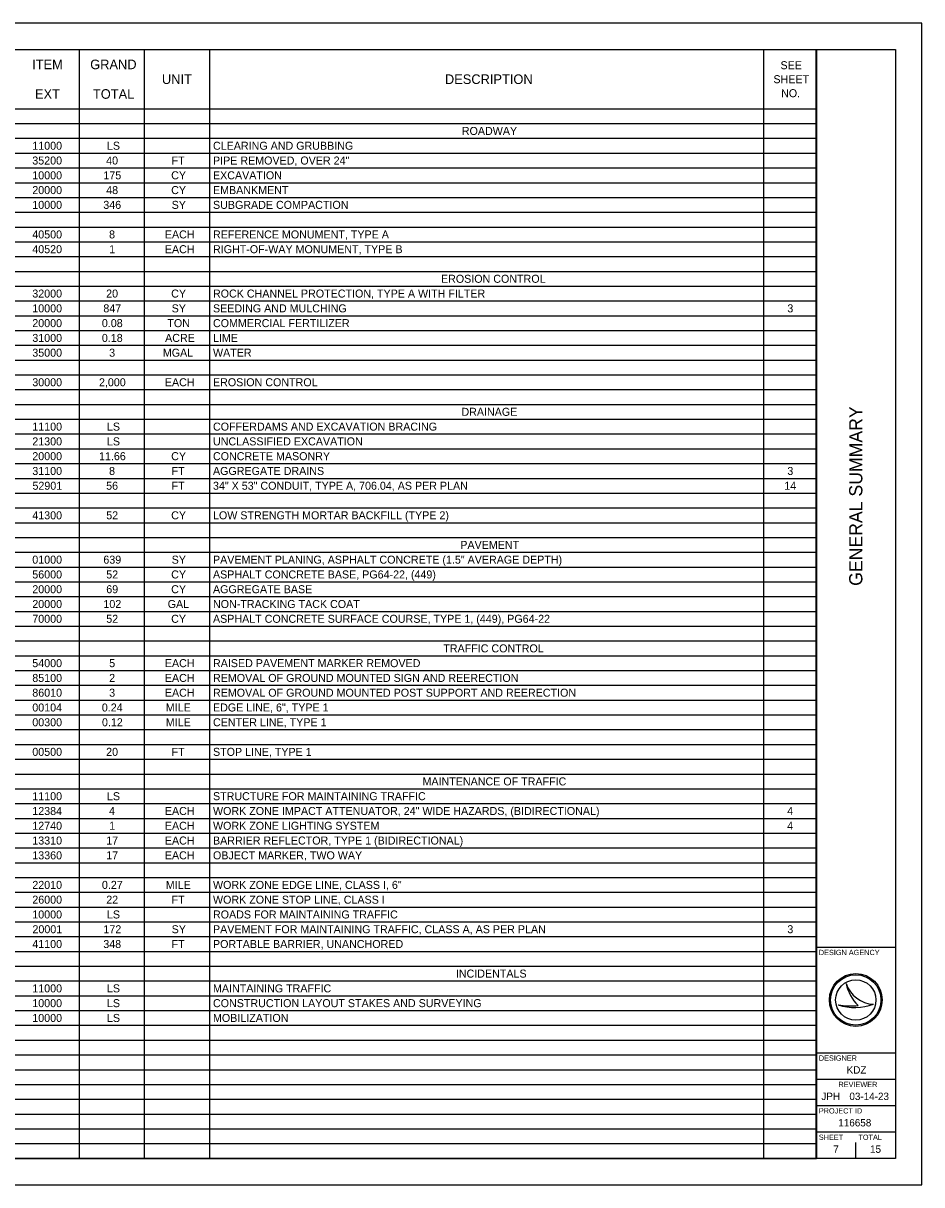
# Model space of a CAD drawing. Extents: x 0 to 34, y 0 to 22.
# Drawn here: x 16.98 to 34, y 0 to 22 of the extents above; entities that cross this region are included whole.
import ezdxf

# ---------------------------------------------------------------- set-up
doc = ezdxf.new("R2010")
doc.units = 0
for name, color, linetype in [('SH_Border', 7, 'Continuous'), ('SH_Cut_Line', 7, 'Continuous'), ('SH_Data', 7, 'Continuous'), ('SH_Text', 7, 'Continuous')]:
    doc.layers.add(name, color=color, linetype=linetype)

msp = doc.modelspace()

# ---------------------------------------------------------------- linework, layer by layer
at = {"layer": 'SH_Border'}
for p, q in [((32, 0.5), (32, 21.5)), ((32, 4.5), (33.5, 4.5)), ((32, 2.5), (33.5, 2.5)), ((32, 2), (33.5, 2)), ((32, 1.5), (33.5, 1.5)), ((32, 1), (33.5, 1))]:
    msp.add_line(p, q, dxfattribs=at)
msp.add_lwpolyline([(1.5, 21.5), (33.5, 21.5), (33.5, 0.5), (1.5, 0.5)], close=True, dxfattribs=at)
at = {"layer": 'SH_Cut_Line'}
msp.add_lwpolyline([(0, 0), (34, 0), (34, 22), (0, 22)], close=True, dxfattribs=at)
at = {"layer": 'SH_Data'}
for p, q in [((32.567, 3.81), (32.567, 3.81)), ((32.417, 3.41), (32.417, 3.41)), ((32.75, 3.5), (32.75, 3.5)), ((33.087, 3.419), (33.087, 3.419)), ((32.375, 0.675), (32.375, 0.675)), ((32.75, 0.5), (32.75, 0.8))]:
    msp.add_line(p, q, dxfattribs=at)
for radius in [0.5, 0.477, 0.477, 0.382]:
    msp.add_circle((32.75, 3.5), radius, dxfattribs=at)
for centre, radius, start, end in [((33.116, 3.998), 0.58, 198.9257, 198.9319), ((33.347, 3.97), 0.796, 191.6379, 191.6421), ((33.116, 3.998), 0.58, 198.9319, 267.1657), ((33.347, 3.97), 0.796, 191.6421, 226.0947), ((32.739, 4.37), 1.013, 251.4576, 290.0832), ((32.648, 4.654), 1.266, 259.4964, 259.4995), ((32.739, 4.37), 1.013, 251.4527, 251.4576), ((32.648, 4.654), 1.266, 259.4995, 276.6672)]:
    msp.add_arc(centre, radius, start, end, dxfattribs=at)
at = {"layer": 'SH_Text'}
for p, q in [((1.5, 21.5), (32.004, 21.5)), ((18.036, 21.5), (18.036, 0.5)), ((19.272, 21.5), (19.272, 0.5)), ((20.507, 21.5), (20.507, 0.5)), ((30.999, 21.5), (30.999, 0.5)), ((32.004, 21.5), (32.004, 0.5)), ((1.5, 20.38), (32.004, 20.38)), ((1.5, 20.1), (32.004, 20.1)), ((1.5, 19.82), (32.004, 19.82)), ((1.5, 19.54), (32.004, 19.54)), ((1.5, 19.26), (32.004, 19.26)), ((1.5, 18.98), (32.004, 18.98)), ((1.5, 18.7), (32.004, 18.7)), ((1.5, 18.42), (32.004, 18.42)), ((1.5, 18.14), (32.004, 18.14)), ((1.5, 17.86), (32.004, 17.86)), ((1.5, 17.58), (32.004, 17.58)), ((1.5, 17.3), (32.004, 17.3)), ((1.5, 17.02), (32.004, 17.02)), ((1.5, 16.74), (32.004, 16.74)), ((1.5, 16.46), (32.004, 16.46)), ((1.5, 16.18), (32.004, 16.18)), ((1.5, 15.9), (32.004, 15.9)), ((1.5, 15.62), (32.004, 15.62)), ((1.5, 15.34), (32.004, 15.34)), ((1.5, 15.06), (32.004, 15.06)), ((1.5, 14.78), (32.004, 14.78)), ((1.5, 14.5), (32.004, 14.5)), ((1.5, 14.22), (32.004, 14.22)), ((1.5, 13.94), (32.004, 13.94)), ((1.5, 13.66), (32.004, 13.66)), ((1.5, 13.38), (32.004, 13.38)), ((1.5, 13.1), (32.004, 13.1)), ((1.5, 12.82), (32.004, 12.82)), ((1.5, 12.54), (32.004, 12.54)), ((1.5, 12.26), (32.004, 12.26)), ((1.5, 11.98), (32.004, 11.98)), ((1.5, 11.7), (32.004, 11.7)), ((1.5, 11.42), (32.004, 11.42)), ((1.5, 11.14), (32.004, 11.14)), ((1.5, 10.86), (32.004, 10.86)), ((1.5, 10.58), (32.004, 10.58)), ((1.5, 10.3), (32.004, 10.3)), ((1.5, 10.02), (32.004, 10.02)), ((1.5, 9.74), (32.004, 9.74)), ((1.5, 9.46), (32.004, 9.46)), ((1.5, 9.18), (32.004, 9.18)), ((1.5, 8.9), (32.004, 8.9)), ((1.5, 8.62), (32.004, 8.62)), ((1.5, 8.34), (32.004, 8.34)), ((1.5, 8.06), (32.004, 8.06)), ((1.5, 7.78), (32.004, 7.78)), ((1.5, 7.5), (32.004, 7.5)), ((1.5, 7.22), (32.004, 7.22)), ((1.5, 6.94), (32.004, 6.94)), ((1.5, 6.66), (32.004, 6.66)), ((1.5, 6.38), (32.004, 6.38)), ((1.5, 6.1), (32.004, 6.1)), ((1.5, 5.82), (32.004, 5.82)), ((1.5, 5.54), (32.004, 5.54)), ((1.5, 5.26), (32.004, 5.26)), ((1.5, 4.98), (32.004, 4.98)), ((1.5, 4.7), (32.004, 4.7)), ((1.5, 4.42), (32.004, 4.42)), ((1.5, 4.14), (32.004, 4.14)), ((1.5, 3.86), (32.004, 3.86)), ((1.5, 3.58), (32.004, 3.58)), ((1.5, 3.3), (32.004, 3.3)), ((1.5, 3.02), (32.004, 3.02)), ((1.5, 2.74), (32.004, 2.74)), ((1.5, 2.46), (32.004, 2.46)), ((1.5, 2.18), (32.004, 2.18)), ((1.5, 1.9), (32.004, 1.9)), ((1.5, 1.62), (32.004, 1.62)), ((1.5, 1.34), (32.004, 1.34)), ((1.5, 1.06), (32.004, 1.06)), ((1.5, 0.78), (32.004, 0.78)), ((1.5, 0.5), (32.004, 0.5))]:
    msp.add_line(p, q, dxfattribs=at)

# ---------------------------------------------------------------- texts
at = {"layer": 'SH_Data'}
msp.add_text('GENERAL SUMMARY', height=0.25, rotation=90, dxfattribs=at).set_placement((32.875, 11.344))
for s, height, p in [('DESIGN AGENCY', 0.1, (32.05, 4.35)), ('DESIGNER', 0.1, (32.05, 2.35)), ('KDZ', 0.14, (32.577, 2.105)), ('REVIEWER', 0.1, (32.422, 1.85)), ('JPH', 0.14, (32.098, 1.605)), ('03-14-23', 0.14, (32.629, 1.605)), ('PROJECT ID', 0.1, (32.05, 1.35)), ('116658', 0.14, (32.419, 1.105)), ('SHEET', 0.1, (32.05, 0.85)), ('TOTAL', 0.1, (32.8, 0.85)), ('7', 0.14, (32.324, 0.605)), ('15', 0.14, (33.02, 0.605))]:
    msp.add_text(s, height=height, dxfattribs=at).set_placement(p)
at = {"layer": 'SH_Text'}
for s, height, p in [('ITEM', 0.1818, (17.147, 21.129)), ('GRAND', 0.1818, (18.247, 21.129)), ('SEE ', 0.1515, (31.324, 21.129)), ('UNIT', 0.1818, (19.606, 20.849)), ('DESCRIPTION', 0.18184, (24.967, 20.849)), ('SHEET ', 0.1515, (31.19, 20.864)), ('EXT', 0.1818, (17.201, 20.569)), ('TOTAL', 0.1818, (18.299, 20.569)), ('NO.', 0.1515, (31.335, 20.599)), ('ROADWAY', 0.1515, (25.287, 19.884)), ('11000', 0.1515, (17.15, 19.604)), ('LS', 0.1515, (18.564, 19.604)), ('CLEARING AND GRUBBING', 0.15153, (20.573, 19.604)), ('35200', 0.1515, (17.15, 19.324)), ('40', 0.1515, (18.549, 19.324)), ('FT', 0.1515, (19.789, 19.324)), ('PIPE REMOVED, OVER 24"', 0.15153, (20.573, 19.324)), ('10000', 0.1515, (17.15, 19.044)), ('175', 0.1515, (18.497, 19.044)), ('CY', 0.1515, (19.781, 19.044)), ('EXCAVATION', 0.1515, (20.573, 19.044)), ('20000', 0.1515, (17.15, 18.764)), ('48', 0.1515, (18.55, 18.764)), ('CY', 0.1515, (19.781, 18.764)), ('EMBANKMENT', 0.1515, (20.573, 18.764)), ('10000', 0.1515, (17.15, 18.484)), ('346', 0.1515, (18.495, 18.484)), ('SY', 0.1515, (19.79, 18.484)), ('SUBGRADE COMPACTION', 0.15153, (20.573, 18.484)), ('40500', 0.1515, (17.15, 17.924)), ('8', 0.152, (18.604, 17.924)), ('EACH', 0.1515, (19.661, 17.924)), ('REFERENCE MONUMENT, TYPE A', 0.15153, (20.573, 17.924)), ('40520', 0.1515, (17.15, 17.644)), ('1', 0.152, (18.606, 17.644)), ('EACH', 0.1515, (19.661, 17.644)), ('RIGHT-OF-WAY MONUMENT, TYPE B', 0.15153, (20.573, 17.644)), ('EROSION CONTROL', 0.15153, (24.892, 17.084)), ('32000', 0.1515, (17.15, 16.804)), ('20', 0.1515, (18.549, 16.804)), ('CY', 0.1515, (19.781, 16.804)), ('ROCK CHANNEL PROTECTION, TYPE A WITH FILTER', 0.15153, (20.573, 16.804)), ('10000', 0.1515, (17.15, 16.524)), ('847', 0.1515, (18.496, 16.524)), ('SY', 0.1515, (19.79, 16.524)), ('SEEDING AND MULCHING', 0.15153, (20.573, 16.524)), ('3', 0.152, (31.453, 16.524)), ('20000', 0.1515, (17.15, 16.244)), ('0.08', 0.1515, (18.468, 16.244)), ('TON', 0.1515, (19.709, 16.244)), ('COMMERCIAL FERTILIZER', 0.15153, (20.573, 16.244)), ('31000', 0.1515, (17.15, 15.964)), ('0.18', 0.1515, (18.468, 15.964)), ('ACRE', 0.1515, (19.666, 15.964)), ('LIME', 0.1515, (20.573, 15.964)), ('35000', 0.1515, (17.15, 15.684)), ('3', 0.152, (18.606, 15.684)), ('MGAL', 0.1515, (19.623, 15.684)), ('WATER', 0.1515, (20.573, 15.684)), ('30000', 0.1515, (17.15, 15.124)), ('2,000', 0.1515, (18.413, 15.124)), ('EACH', 0.1515, (19.661, 15.124)), ('EROSION CONTROL', 0.15153, (20.573, 15.124)), ('DRAINAGE', 0.1515, (25.28, 14.564)), ('11100', 0.1515, (17.15, 14.284)), ('LS', 0.1515, (18.564, 14.284)), ('COFFERDAMS AND EXCAVATION BRACING', 0.15153, (20.573, 14.284)), ('21300', 0.1515, (17.15, 14.004)), ('LS', 0.1515, (18.564, 14.004)), ('UNCLASSIFIED EXCAVATION', 0.15153, (20.573, 14.004)), ('20000', 0.1515, (17.15, 13.724)), ('11.66', 0.1515, (18.414, 13.724)), ('CY', 0.1515, (19.781, 13.724)), ('CONCRETE MASONRY', 0.15153, (20.573, 13.724)), ('31100', 0.1515, (17.15, 13.444)), ('8', 0.152, (18.604, 13.444)), ('FT', 0.1515, (19.789, 13.444)), ('AGGREGATE DRAINS', 0.15153, (20.573, 13.444)), ('3', 0.152, (31.453, 13.444)), ('52901', 0.1515, (17.153, 13.164)), ('56', 0.1515, (18.549, 13.164)), ('FT', 0.1515, (19.789, 13.164)), ('34" X 53" CONDUIT, TYPE A, 706.04, AS PER PLAN', 0.15153, (20.573, 13.164)), ('14', 0.1515, (31.395, 13.164)), ('LOW STRENGTH MORTAR BACKFILL (TYPE 2)', 0.15153, (20.573, 12.604)), ('41300', 0.1515, (17.15, 12.604)), ('52', 0.1515, (18.551, 12.604)), ('CY', 0.1515, (19.781, 12.604)), ('PAVEMENT', 0.1515, (25.258, 12.044)), ('01000', 0.1515, (17.15, 11.764)), ('639', 0.1515, (18.496, 11.764)), ('SY', 0.1515, (19.79, 11.764)), ('PAVEMENT PLANING, ASPHALT CONCRETE (1.5" AVERAGE DEPTH)', 0.15153, (20.573, 11.764)), ('56000', 0.1515, (17.15, 11.484)), ('52', 0.1515, (18.551, 11.484)), ('CY', 0.1515, (19.781, 11.484)), ('ASPHALT CONCRETE BASE, PG64-22, (449)', 0.15153, (20.573, 11.484)), ('20000', 0.1515, (17.15, 11.204)), ('69', 0.1515, (18.551, 11.204)), ('CY', 0.1515, (19.781, 11.204)), ('AGGREGATE BASE', 0.15153, (20.573, 11.204)), ('20000', 0.1515, (17.15, 10.924)), ('102', 0.1515, (18.497, 10.924)), ('GAL', 0.1515, (19.715, 10.924)), ('NON-TRACKING TACK COAT', 0.15153, (20.573, 10.924)), ('70000', 0.1515, (17.15, 10.644)), ('52', 0.1515, (18.551, 10.644)), ('CY', 0.1515, (19.781, 10.644)), ('ASPHALT CONCRETE SURFACE COURSE, TYPE 1, (449), PG64-22', 0.15153, (20.573, 10.644)), ('TRAFFIC CONTROL', 0.15153, (24.936, 10.084)), ('54000', 0.1515, (17.15, 9.804)), ('5', 0.152, (18.606, 9.804)), ('EACH', 0.1515, (19.661, 9.804)), ('RAISED PAVEMENT MARKER REMOVED', 0.15153, (20.573, 9.804)), ('85100', 0.1515, (17.15, 9.524)), ('2', 0.152, (18.606, 9.524)), ('EACH', 0.1515, (19.661, 9.524)), ('REMOVAL OF GROUND MOUNTED SIGN AND REERECTION', 0.15153, (20.573, 9.524)), ('86010', 0.1515, (17.15, 9.244)), ('3', 0.152, (18.606, 9.244)), ('EACH', 0.1515, (19.661, 9.244)), ('REMOVAL OF GROUND MOUNTED POST SUPPORT AND REERECTION', 0.15153, (20.573, 9.244)), ('00104', 0.1515, (17.15, 8.964)), ('0.24', 0.1515, (18.467, 8.964)), ('MILE', 0.1515, (19.679, 8.964)), ('EDGE LINE, 6", TYPE 1', 0.15153, (20.573, 8.964)), ('00300', 0.1515, (17.15, 8.684)), ('0.12', 0.1515, (18.47, 8.684)), ('MILE', 0.1515, (19.679, 8.684)), ('CENTER LINE, TYPE 1', 0.15153, (20.573, 8.684)), ('00500', 0.1515, (17.15, 8.124)), ('20', 0.1515, (18.549, 8.124)), ('FT', 0.1515, (19.789, 8.124)), ('STOP LINE, TYPE 1', 0.15153, (20.573, 8.124)), ('MAINTENANCE OF TRAFFIC', 0.15153, (24.542, 7.564)), ('11100', 0.1515, (17.15, 7.284)), ('LS', 0.1515, (18.564, 7.284)), ('STRUCTURE FOR MAINTAINING TRAFFIC', 0.15153, (20.573, 7.284)), ('12384', 0.1515, (17.15, 7.004)), ('4', 0.152, (18.603, 7.004)), ('EACH', 0.1515, (19.661, 7.004)), ('WORK ZONE IMPACT ATTENUATOR, 24" WIDE HAZARDS, (BIDIRECTIONAL)', 0.15153, (20.573, 7.004)), ('4', 0.152, (31.45, 7.004)), ('12740', 0.1515, (17.15, 6.724)), ('1', 0.152, (18.606, 6.724)), ('EACH', 0.1515, (19.661, 6.724)), ('WORK ZONE LIGHTING SYSTEM', 0.15153, (20.573, 6.724)), ('4', 0.152, (31.45, 6.724)), ('BARRIER REFLECTOR, TYPE 1 (BIDIRECTIONAL)', 0.15153, (20.573, 6.444)), ('13310', 0.1515, (17.15, 6.444)), ('17', 0.1515, (18.55, 6.444)), ('EACH', 0.1515, (19.661, 6.444)), ('13360', 0.1515, (17.15, 6.164)), ('17', 0.1515, (18.55, 6.164)), ('EACH', 0.1515, (19.661, 6.164)), ('OBJECT MARKER, TWO WAY', 0.15153, (20.573, 6.164)), ('22010', 0.1515, (17.15, 5.604)), ('0.27', 0.1515, (18.469, 5.604)), ('MILE', 0.1515, (19.679, 5.604)), ('WORK ZONE EDGE LINE, CLASS I, 6"', 0.15153, (20.573, 5.604)), ('26000', 0.1515, (17.15, 5.324)), ('22', 0.1515, (18.551, 5.324)), ('FT', 0.1515, (19.789, 5.324)), ('WORK ZONE STOP LINE, CLASS I', 0.15153, (20.573, 5.324)), ('10000', 0.1515, (17.15, 5.044)), ('LS', 0.1515, (18.564, 5.044)), ('ROADS FOR MAINTAINING TRAFFIC', 0.15153, (20.573, 5.044)), ('20001', 0.1515, (17.153, 4.764)), ('172', 0.1515, (18.497, 4.764)), ('SY', 0.1515, (19.79, 4.764)), ('PAVEMENT FOR MAINTAINING TRAFFIC, CLASS A, AS PER PLAN', 0.15153, (20.573, 4.764)), ('3', 0.152, (31.453, 4.764)), ('41100', 0.1515, (17.15, 4.484)), ('348', 0.1515, (18.495, 4.484)), ('FT', 0.1515, (19.789, 4.484)), ('PORTABLE BARRIER, UNANCHORED', 0.15153, (20.573, 4.484)), ('INCIDENTALS', 0.15153, (25.174, 3.924)), ('11000', 0.1515, (17.15, 3.644)), ('LS', 0.1515, (18.564, 3.644)), ('MAINTAINING TRAFFIC', 0.15153, (20.573, 3.644)), ('10000', 0.1515, (17.15, 3.364)), ('LS', 0.1515, (18.564, 3.364)), ('CONSTRUCTION LAYOUT STAKES AND SURVEYING', 0.15153, (20.573, 3.364)), ('10000', 0.1515, (17.15, 3.084)), ('LS', 0.1515, (18.564, 3.084)), ('MOBILIZATION', 0.15153, (20.573, 3.084))]:
    msp.add_text(s, height=height, dxfattribs=at).set_placement(p)

doc.saveas('drawing.dxf')
